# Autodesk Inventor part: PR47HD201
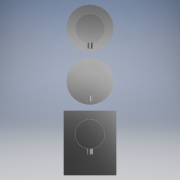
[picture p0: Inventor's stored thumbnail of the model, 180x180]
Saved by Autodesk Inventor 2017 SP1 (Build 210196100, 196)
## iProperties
Created: 2018-11
Part Number: PR47HD201
Material: Generico
Document SubType Name: Modeling
Designer: CIANI A.
Density: 1 g/cm^3
Appearance: Default
Author: CIANI A.
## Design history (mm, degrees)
feature "Base4"
node "Solido1"
node "Solido5"
